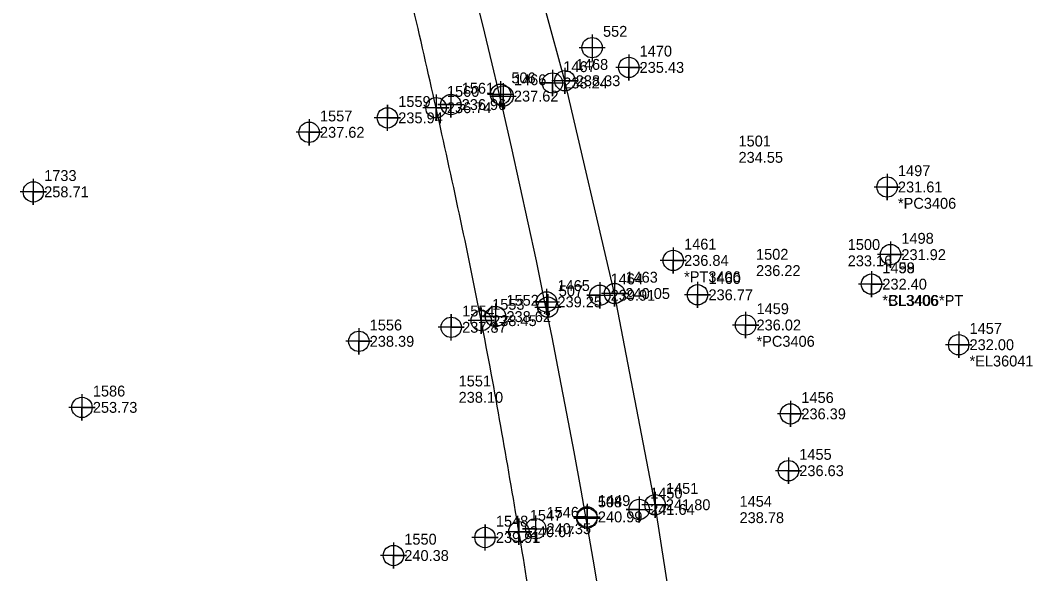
# Model space of a CAD drawing. Extents: x 2130621 to 2131998, y 642516 to 644503.
# Drawn here: x 2131080.5 to 2131313.1, y 643604.3 to 643731.5 of the extents above; entities that cross this region are included whole.
import ezdxf

# ---------------------------------------------------------------- set-up
doc = ezdxf.new("R2010")
doc.units = 0
for name, color, linetype in [('Cogo Default Point CELL', 7, 'Continuous'), ('COGO Default Point Number', 7, 'Continuous'), ('Exist Other Culture Area Outline Cogo Comment', 7, 'Continuous'), ('Exist Other Culture Area Outline Cogo Elevation', 7, 'Continuous'), ('Exist Other Culture Area Outline Cogo Number', 7, 'Continuous'), ('Exist Other Culture Area Outline Cogo Point CELL', 7, 'Continuous'), ('Exist Other Culture Fence Line Cogo Elevation', 7, 'Continuous'), ('Exist Other Culture Fence Line Cogo Number', 7, 'Continuous'), ('Exist Other Culture Fence Line Cogo Point CELL', 7, 'Continuous'), ('Exist Other Culture Sign Cogo Elevation', 7, 'Continuous'), ('Exist Other Culture Sign Cogo Number', 7, 'Continuous'), ('Exist Roads EOP', 7, 'Continuous'), ('Exist Roads EOP Cogo Elevation', 7, 'Continuous'), ('Exist Roads EOP Cogo Number', 7, 'Continuous'), ('Exist Roads EOP Cogo Point CELL', 7, 'Continuous'), ('Exist Roads EOT Cogo Elevation', 7, 'Continuous'), ('Exist Roads EOT Cogo Number', 7, 'Continuous'), ('Exist Roads EOT Cogo Point CELL', 7, 'Continuous'), ('Exist Roads Soil Cogo Elevation', 7, 'Continuous'), ('Exist Roads Soil Cogo Number', 7, 'Continuous'), ('Exist Roads Soil Cogo Point CELL', 7, 'Continuous'), ('Exist Vegetation Tree Cogo Elevation', 7, 'Continuous'), ('Exist Vegetation Tree Cogo Number', 7, 'Continuous'), ('Exist Vegetation Woods Line Cogo Comment', 7, 'Continuous'), ('Exist Vegetation Woods Line Cogo Elevation', 7, 'Continuous'), ('Exist Vegetation Woods Line Cogo Number', 7, 'Continuous'), ('Exist Vegetation Woods Line Cogo Point CELL', 7, 'Continuous'), ('Prop Horizontal Alignment', 7, 'Continuous')]:
    doc.layers.add(name, color=color, linetype=linetype)

msp = doc.modelspace()

# ---------------------------------------------------------------- linework, layer by layer
at = {"layer": 'Cogo Default Point CELL'}
for points in [[(2131211.87, 643728.21), (2131211.87, 643725.21)], [(2131211.87, 643728.21), (2131211.87, 643725.21)], [(2131208.87, 643725.21), (2131211.87, 643725.21)], [(2131208.87, 643725.21), (2131211.87, 643725.21)], [(2131211.87, 643725.21), (2131214.87, 643725.21)], [(2131211.87, 643725.21), (2131211.87, 643722.21)], [(2131211.87, 643725.21), (2131214.87, 643725.21)], [(2131211.87, 643725.21), (2131211.87, 643722.21)], [(2131190.82, 643717.51), (2131190.82, 643714.51)], [(2131187.82, 643714.51), (2131190.82, 643714.51)], [(2131190.82, 643714.51), (2131193.82, 643714.51)], [(2131190.82, 643714.51), (2131190.82, 643711.51)], [(2131201.71, 643668.59), (2131201.71, 643665.59)], [(2131198.71, 643665.59), (2131201.71, 643665.59)], [(2131201.71, 643665.59), (2131204.71, 643665.59)], [(2131201.71, 643665.59), (2131201.71, 643662.59)], [(2131210.69, 643620.09), (2131210.69, 643617.09)], [(2131207.69, 643617.09), (2131210.69, 643617.09)], [(2131210.69, 643617.09), (2131213.69, 643617.09)], [(2131210.69, 643617.09), (2131210.69, 643614.09)]]:
    msp.add_lwpolyline(points, dxfattribs=at)
for centre in [(2131211.87, 643725.21), (2131211.87, 643725.21), (2131190.82, 643714.51), (2131201.71, 643665.59), (2131210.69, 643617.09)]:
    msp.add_circle(centre, 2.34, dxfattribs=at)
at = {"layer": 'Exist Other Culture Area Outline Cogo Point CELL'}
for points in [[(2131220.29, 643723.67), (2131220.29, 643717.67), (2131220.29, 643720.67), (2131223.29, 643720.67), (2131217.29, 643720.67)], [(2131279.65, 643696.19), (2131279.65, 643690.19), (2131279.65, 643693.19), (2131282.65, 643693.19), (2131276.65, 643693.19)], [(2131280.44, 643680.65), (2131280.44, 643674.65), (2131280.44, 643677.65), (2131283.44, 643677.65), (2131277.44, 643677.65)], [(2131230.51, 643679.32), (2131230.51, 643673.32), (2131230.51, 643676.32), (2131233.51, 643676.32), (2131227.51, 643676.32)], [(2131276.07, 643673.87), (2131276.07, 643667.87), (2131276.07, 643670.87), (2131279.07, 643670.87), (2131273.07, 643670.87)], [(2131276.07, 643673.87), (2131276.07, 643667.87), (2131276.07, 643670.87), (2131279.07, 643670.87), (2131273.07, 643670.87)], [(2131236.11, 643671.42), (2131236.11, 643665.42), (2131236.11, 643668.42), (2131239.11, 643668.42), (2131233.11, 643668.42)], [(2131247.15, 643664.48), (2131247.15, 643658.48), (2131247.15, 643661.48), (2131250.15, 643661.48), (2131244.15, 643661.48)]]:
    msp.add_lwpolyline(points, dxfattribs=at)
for centre in [(2131220.29, 643720.67), (2131279.65, 643693.19), (2131280.44, 643677.65), (2131230.51, 643676.32), (2131276.07, 643670.87), (2131276.07, 643670.87), (2131236.11, 643668.42), (2131247.15, 643661.48)]:
    msp.add_circle(centre, 2.34, dxfattribs=at)
at = {"layer": 'Exist Other Culture Fence Line Cogo Point CELL'}
for points in [[(2131083.47, 643695.07), (2131083.47, 643689.07), (2131083.47, 643692.07), (2131086.47, 643692.07), (2131080.47, 643692.07)], [(2131094.65, 643645.55), (2131094.65, 643639.55), (2131094.65, 643642.55), (2131097.65, 643642.55), (2131091.65, 643642.55)]]:
    msp.add_lwpolyline(points, dxfattribs=at)
for centre in [(2131083.47, 643692.07), (2131094.65, 643642.55)]:
    msp.add_circle(centre, 2.34, dxfattribs=at)
at = {"layer": 'Exist Roads EOP'}
msp.add_lwpolyline([(2131264.27, 643222.56), (2131259.88, 643269.33), (2131257.02, 643319.4), (2131254.26, 643369.65), (2131250.08, 643419.42), (2131246.15, 643469.03), (2131240.84, 643519.13), (2131234.37, 643568.56), (2131226.33, 643620.18), (2131217.03, 643668.71), (2131205.62, 643717.61), (2131192.06, 643767.26), (2131177.97, 643815.09), (2131162.29, 643862.93), (2131145.36, 643910.85), (2131126.91, 643957.29), (2131112.37, 643996.12)], dxfattribs=at)
msp.add_spline([(2131166.25, 643216.7), (2131171.81, 643218.72), (2131182.37, 643223.97), (2131191.81, 643231.15), (2131200.5, 643239.7), (2131208.81, 643249.07), (2131216.07, 643259), (2131218.72, 643264.35), (2131220.54, 643270.1), (2131222.84, 643282.01), (2131224.36, 643293.92), (2131224.88, 643317.79), (2131222.06, 643367.67), (2131218.54, 643416.81), (2131214.32, 643466.35), (2131209.17, 643515.67), (2131202.79, 643565.15), (2131195.05, 643613.99), (2131186.4, 643662.48), (2131176.01, 643711.41), (2131164.62, 643759.89), (2131151.87, 643807.85), (2131137.86, 643855.41), (2131122.57, 643902.86), (2131105.96, 643949.49), (2131091.53, 643988.04)], degree=3, dxfattribs=at)
at = {"layer": 'Exist Roads EOP Cogo Point CELL'}
for points in [[(2131205.62, 643720.61), (2131205.62, 643714.61), (2131205.62, 643717.61), (2131208.62, 643717.61), (2131202.62, 643717.61)], [(2131176.01, 643714.41), (2131176.01, 643708.41), (2131176.01, 643711.41), (2131179.01, 643711.41), (2131173.01, 643711.41)], [(2131217.03, 643671.71), (2131217.03, 643665.71), (2131217.03, 643668.71), (2131220.03, 643668.71), (2131214.03, 643668.71)], [(2131186.4, 643665.48), (2131186.4, 643659.48), (2131186.4, 643662.48), (2131189.4, 643662.48), (2131183.4, 643662.48)], [(2131226.33, 643623.18), (2131226.33, 643617.18), (2131226.33, 643620.18), (2131229.33, 643620.18), (2131223.33, 643620.18)], [(2131195.05, 643616.99), (2131195.05, 643610.99), (2131195.05, 643613.99), (2131198.05, 643613.99), (2131192.05, 643613.99)]]:
    msp.add_lwpolyline(points, dxfattribs=at)
for centre in [(2131205.62, 643717.61), (2131176.01, 643711.41), (2131217.03, 643668.71), (2131186.4, 643662.48), (2131226.33, 643620.18), (2131195.05, 643613.99)]:
    msp.add_circle(centre, 2.34, dxfattribs=at)
at = {"layer": 'Exist Roads EOT Cogo Point CELL'}
for points in [[(2131202.75, 643720.09), (2131202.75, 643714.09), (2131202.75, 643717.09), (2131199.75, 643717.09), (2131205.75, 643717.09)], [(2131179.4, 643715.13), (2131179.4, 643709.13), (2131179.4, 643712.13), (2131176.4, 643712.13), (2131182.4, 643712.13)], [(2131191.41, 643717.08), (2131191.41, 643711.08), (2131191.41, 643714.08), (2131188.41, 643714.08), (2131194.41, 643714.08)], [(2131213.64, 643671.31), (2131213.64, 643665.31), (2131213.64, 643668.31), (2131210.64, 643668.31), (2131216.64, 643668.31)], [(2131201.41, 643669.79), (2131201.41, 643663.79), (2131201.41, 643666.79), (2131198.41, 643666.79), (2131204.41, 643666.79)], [(2131189.69, 643666.41), (2131189.69, 643660.41), (2131189.69, 643663.41), (2131186.69, 643663.41), (2131192.69, 643663.41)], [(2131222.71, 643622.1), (2131222.71, 643616.1), (2131222.71, 643619.1), (2131219.71, 643619.1), (2131225.71, 643619.1)], [(2131210.7, 643620.38), (2131210.7, 643614.38), (2131210.7, 643617.38), (2131207.7, 643617.38), (2131213.7, 643617.38)], [(2131198.9, 643617.68), (2131198.9, 643611.68), (2131198.9, 643614.68), (2131195.9, 643614.68), (2131201.9, 643614.68)]]:
    msp.add_lwpolyline(points, dxfattribs=at)
for centre in [(2131202.75, 643717.09), (2131191.41, 643714.08), (2131179.4, 643712.13), (2131213.64, 643668.31), (2131201.41, 643666.79), (2131189.69, 643663.41), (2131210.7, 643617.38), (2131222.71, 643619.1), (2131198.9, 643614.68)]:
    msp.add_circle(centre, 2.34, dxfattribs=at)
at = {"layer": 'Exist Roads Soil Cogo Point CELL'}
for points in [[(2131164.83, 643706.08), (2131164.83, 643712.08), (2131164.83, 643709.08), (2131167.83, 643709.08), (2131161.83, 643709.08)], [(2131179.51, 643657.95), (2131179.51, 643663.95), (2131179.51, 643660.95), (2131182.51, 643660.95), (2131176.51, 643660.95)], [(2131187.26, 643609.65), (2131187.26, 643615.65), (2131187.26, 643612.65), (2131190.26, 643612.65), (2131184.26, 643612.65)]]:
    msp.add_lwpolyline(points, dxfattribs=at)
for centre in [(2131164.83, 643709.08), (2131179.51, 643660.95), (2131187.26, 643612.65)]:
    msp.add_circle(centre, 2.34, dxfattribs=at)
at = {"layer": 'Exist Vegetation Woods Line Cogo Point CELL'}
for points in [[(2131146.84, 643708.76), (2131146.84, 643702.76), (2131146.84, 643705.76), (2131149.84, 643705.76), (2131143.84, 643705.76)], [(2131158.27, 643660.73), (2131158.27, 643654.73), (2131158.27, 643657.73), (2131161.27, 643657.73), (2131155.27, 643657.73)], [(2131296.1, 643659.95), (2131296.1, 643653.95), (2131296.1, 643656.95), (2131299.1, 643656.95), (2131293.1, 643656.95)], [(2131257.46, 643644.06), (2131257.46, 643638.06), (2131257.46, 643641.06), (2131260.46, 643641.06), (2131254.46, 643641.06)], [(2131256.98, 643631), (2131256.98, 643625), (2131256.98, 643628), (2131259.98, 643628), (2131253.98, 643628)], [(2131166.22, 643611.51), (2131166.22, 643605.51), (2131166.22, 643608.51), (2131169.22, 643608.51), (2131163.22, 643608.51)]]:
    msp.add_lwpolyline(points, dxfattribs=at)
for centre in [(2131146.84, 643705.76), (2131158.27, 643657.73), (2131296.1, 643656.95), (2131257.46, 643641.06), (2131256.98, 643628), (2131166.22, 643608.51)]:
    msp.add_circle(centre, 2.34, dxfattribs=at)
at = {"layer": 'Prop Horizontal Alignment'}
msp.add_arc((2129448.47, 643307.66), 1788.96, 4.14306, 22.49968, dxfattribs=at)

# ---------------------------------------------------------------- texts
at = {"layer": 'COGO Default Point Number'}
for s, p in [('552', (2131214.37, 643727.71)), ('506', (2131193.32, 643717.01)), ('507', (2131204.21, 643668.09)), ('508', (2131213.19, 643619.59))]:
    msp.add_text(s, height=2.5, dxfattribs=at).set_placement(p)
at = {"layer": 'Exist Other Culture Area Outline Cogo Comment'}
for s, p in [('*PC3406', (2131282.15, 643688.19)), ('*PT3406', (2131233.01, 643671.32)), ('*BL3406', (2131278.57, 643665.87)), ('*CL3406*PT', (2131278.57, 643665.87)), ('*PC3406', (2131249.65, 643656.48))]:
    msp.add_text(s, height=2.5, dxfattribs=at).set_placement(p)
at = {"layer": 'Exist Other Culture Area Outline Cogo Elevation'}
for s, p in [('235.43', (2131222.79, 643719.42)), ('231.61', (2131282.15, 643691.94)), ('231.92', (2131282.94, 643676.4)), ('236.84', (2131233.01, 643675.07)), ('232.40', (2131278.57, 643669.62)), ('232.40', (2131278.57, 643669.62)), ('236.77', (2131238.61, 643667.17)), ('236.02', (2131249.65, 643660.23))]:
    msp.add_text(s, height=2.5, dxfattribs=at).set_placement(p)
at = {"layer": 'Exist Other Culture Area Outline Cogo Number'}
for s, p in [('1470', (2131222.79, 643723.17)), ('1497', (2131282.15, 643695.69)), ('1498', (2131282.94, 643680.15)), ('1461', (2131233.01, 643678.82)), ('1458', (2131278.57, 643673.37)), ('1499', (2131278.57, 643673.37)), ('1460', (2131238.61, 643670.92)), ('1459', (2131249.65, 643663.98))]:
    msp.add_text(s, height=2.5, dxfattribs=at).set_placement(p)
at = {"layer": 'Exist Other Culture Fence Line Cogo Elevation'}
for s, p in [('258.71', (2131085.97, 643690.82)), ('253.73', (2131097.15, 643641.3))]:
    msp.add_text(s, height=2.5, dxfattribs=at).set_placement(p)
at = {"layer": 'Exist Other Culture Fence Line Cogo Number'}
for s, p in [('1733', (2131085.97, 643694.57)), ('1586', (2131097.15, 643645.05))]:
    msp.add_text(s, height=2.5, dxfattribs=at).set_placement(p)
at = {"layer": 'Exist Other Culture Sign Cogo Elevation'}
for s, p in [('238.10', (2131181.2, 643643.61)), ('238.78', (2131245.75, 643615.96))]:
    msp.add_text(s, height=2.5, dxfattribs=at).set_placement(p)
at = {"layer": 'Exist Other Culture Sign Cogo Number'}
for s, p in [('1551', (2131181.2, 643647.36)), ('1454', (2131245.75, 643619.71))]:
    msp.add_text(s, height=2.5, dxfattribs=at).set_placement(p)
at = {"layer": 'Exist Roads EOP Cogo Elevation'}
for s, p in [('238.33', (2131208.12, 643716.36)), ('236.74', (2131178.51, 643710.16)), ('240.05', (2131219.53, 643667.46)), ('238.45', (2131188.9, 643661.23)), ('241.80', (2131228.83, 643618.93)), ('240.07', (2131197.55, 643612.74))]:
    msp.add_text(s, height=2.5, dxfattribs=at).set_placement(p)
at = {"layer": 'Exist Roads EOP Cogo Number'}
for s, p in [('1468', (2131208.12, 643720.11)), ('1560', (2131178.51, 643713.91)), ('1463', (2131219.53, 643671.21)), ('1553', (2131188.9, 643664.98)), ('1451', (2131228.83, 643622.68)), ('1547', (2131197.55, 643616.49))]:
    msp.add_text(s, height=2.5, dxfattribs=at).set_placement(p)
at = {"layer": 'Exist Roads EOT Cogo Elevation'}
for s, p in [('238.24', (2131205.25, 643715.84)), ('237.62', (2131193.91, 643712.83)), ('236.96', (2131181.9, 643710.88)), ('239.91', (2131216.14, 643667.06)), ('239.25', (2131203.91, 643665.54)), ('238.62', (2131192.19, 643662.16)), ('241.64', (2131225.21, 643617.85)), ('240.99', (2131213.2, 643616.13)), ('240.35', (2131201.4, 643613.43))]:
    msp.add_text(s, height=2.5, dxfattribs=at).set_placement(p)
at = {"layer": 'Exist Roads EOT Cogo Number'}
for s, p in [('1467', (2131205.25, 643719.59)), ('1561', (2131181.9, 643714.63)), ('1466', (2131193.91, 643716.58)), ('1464', (2131216.14, 643670.81)), ('1465', (2131203.91, 643669.29)), ('1552', (2131192.19, 643665.91)), ('1450', (2131225.21, 643621.6)), ('1449', (2131213.2, 643619.88)), ('1546', (2131201.4, 643617.18))]:
    msp.add_text(s, height=2.5, dxfattribs=at).set_placement(p)
at = {"layer": 'Exist Roads Soil Cogo Elevation'}
for s, p in [('235.94', (2131167.33, 643707.83)), ('237.87', (2131182.01, 643659.7)), ('239.91', (2131189.76, 643611.4))]:
    msp.add_text(s, height=2.5, dxfattribs=at).set_placement(p)
at = {"layer": 'Exist Roads Soil Cogo Number'}
for s, p in [('1559', (2131167.33, 643711.58)), ('1554', (2131182.01, 643663.45)), ('1548', (2131189.76, 643615.15))]:
    msp.add_text(s, height=2.5, dxfattribs=at).set_placement(p)
at = {"layer": 'Exist Vegetation Tree Cogo Elevation'}
for s, p in [('234.55', (2131245.51, 643698.75)), ('233.16', (2131270.61, 643674.97)), ('236.22', (2131249.54, 643672.73))]:
    msp.add_text(s, height=2.5, dxfattribs=at).set_placement(p)
at = {"layer": 'Exist Vegetation Tree Cogo Number'}
for s, p in [('1501', (2131245.51, 643702.5)), ('1500', (2131270.61, 643678.72)), ('1502', (2131249.54, 643676.48))]:
    msp.add_text(s, height=2.5, dxfattribs=at).set_placement(p)
at = {"layer": 'Exist Vegetation Woods Line Cogo Comment'}
msp.add_text('*EL36041', height=2.5, dxfattribs=at).set_placement((2131298.6, 643651.95))
at = {"layer": 'Exist Vegetation Woods Line Cogo Elevation'}
for s, p in [('237.62', (2131149.34, 643704.51)), ('238.39', (2131160.77, 643656.48)), ('232.00', (2131298.6, 643655.7)), ('236.39', (2131259.96, 643639.81)), ('236.63', (2131259.48, 643626.75)), ('240.38', (2131168.72, 643607.26))]:
    msp.add_text(s, height=2.5, dxfattribs=at).set_placement(p)
at = {"layer": 'Exist Vegetation Woods Line Cogo Number'}
for s, p in [('1557', (2131149.34, 643708.26)), ('1556', (2131160.77, 643660.23)), ('1457', (2131298.6, 643659.45)), ('1456', (2131259.96, 643643.56)), ('1455', (2131259.48, 643630.5)), ('1550', (2131168.72, 643611.01))]:
    msp.add_text(s, height=2.5, dxfattribs=at).set_placement(p)

doc.saveas('drawing.dxf')
